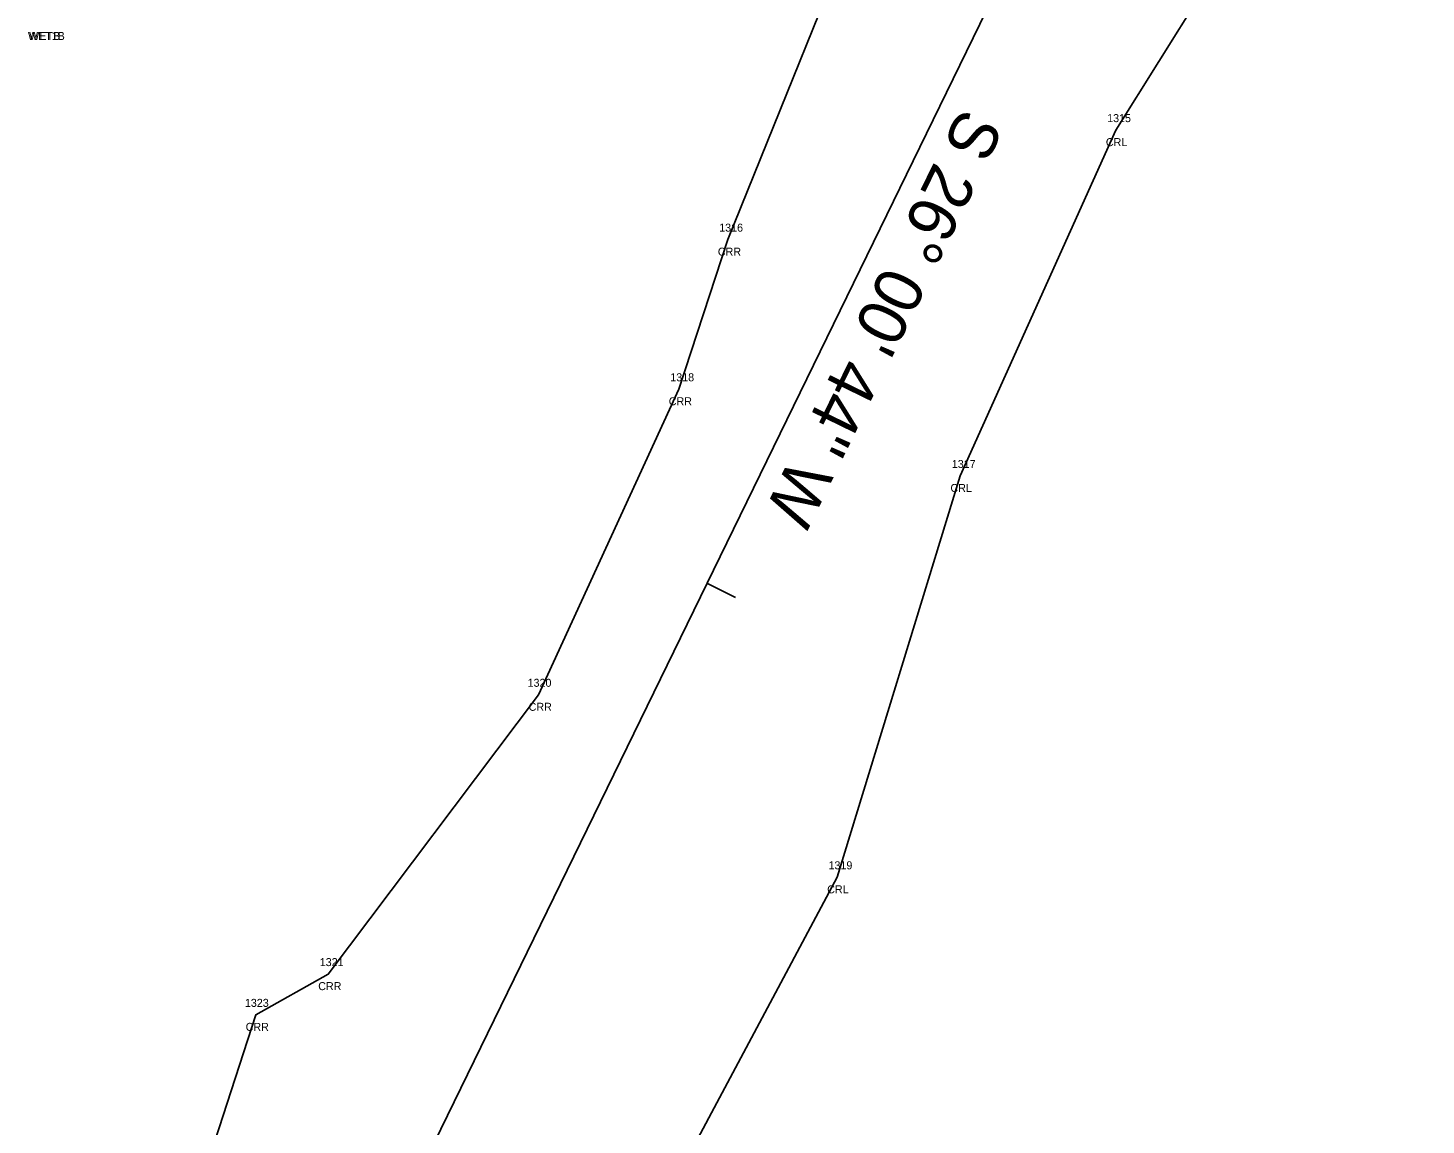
# Model space of a CAD drawing. Extents: x 1964982 to 1970452, y 1116335 to 1119906.
# Drawn here: x 1967698.9 to 1967873.6, y 1117597.5 to 1117734.5 of the extents above; entities that cross this region are included whole.
import ezdxf

# ---------------------------------------------------------------- set-up
doc = ezdxf.new("R2010")
doc.units = 0
for name, color, linetype in [('RD_EX_DV_Prop', 7, 'Continuous'), ('RD_EX_H2O', 7, 'Continuous'), ('RD_EX_H2O_txCode', 7, 'Continuous'), ('RD_EX_H2O_WetLd_txCode', 7, 'Continuous'), ('RD_HC_CL', 7, 'Continuous'), ('RD_HC_Data', 7, 'Continuous'), ('RD_SMD_Locator', 7, 'Continuous')]:
    doc.layers.add(name, color=color, linetype=linetype)

msp = doc.modelspace()

# ---------------------------------------------------------------- linework, layer by layer
at = {"layer": 'RD_EX_DV_Prop'}
msp.add_line((1967849.81, 1117800.6), (1967729.31, 1117553.65), dxfattribs=at)
at = {"layer": 'RD_EX_H2O'}
for points in [[(1967794.3, 1117875.45), (1967796.63, 1117853.43), (1967809.67, 1117835.4), (1967828.83, 1117808.28), (1967805.08, 1117754.56), (1967786.33, 1117708.04), (1967780.19, 1117689.35), (1967762.68, 1117651.19), (1967736.39, 1117616.3), (1967727.33, 1117611.21), (1967715.04, 1117573.35), (1967731.01, 1117514.73), (1967775.86, 1117468.11), (1967793.29, 1117458.88), (1967816.39, 1117454.18)], [(1967873.55, 1117813.3), (1967873.54, 1117810.73), (1967868.98, 1117791.48), (1967856.29, 1117756.05), (1967834.78, 1117721.72), (1967815.36, 1117678.52), (1967799.96, 1117628.39), (1967778.25, 1117587.63), (1967771.33, 1117582.11), (1967756.46, 1117564.6), (1967764.36, 1117543.85), (1967795.97, 1117517.33), (1967805.92, 1117513.21), (1967828.95, 1117503.56)]]:
    msp.add_lwpolyline(points, dxfattribs=at)
at = {"layer": 'RD_HC_CL'}
msp.add_line((1967849.81, 1117800.6), (1967729.31, 1117553.65), dxfattribs=at)
at = {"layer": 'RD_HC_Data'}
msp.add_line((1967783.7, 1117665.12), (1967787.29, 1117663.36), dxfattribs=at)
at = {"layer": 'RD_SMD_Locator'}
for centre in [(1967834.78, 1117721.72), (1967786.33, 1117708.04), (1967780.19, 1117689.35), (1967815.36, 1117678.52), (1967762.68, 1117651.19), (1967799.96, 1117628.39), (1967736.39, 1117616.3), (1967727.33, 1117611.21)]:
    msp.add_circle(centre, 0.001, dxfattribs=at)

# ---------------------------------------------------------------- texts
at = {"layer": 'RD_EX_H2O_txCode'}
for s, p in [('1315', (1967833.71, 1117722.72)), ('CRL', (1967833.55, 1117719.72)), ('1316', (1967785.24, 1117709.04)), ('CRR', (1967785.07, 1117706.04)), ('1318', (1967779.13, 1117690.35)), ('CRR', (1967778.94, 1117687.35)), ('1317', (1967814.3, 1117679.52)), ('CRL', (1967814.13, 1117676.52)), ('1320', (1967761.3, 1117652.19)), ('CRR', (1967761.43, 1117649.19)), ('1319', (1967798.9, 1117629.39)), ('CRL', (1967798.73, 1117626.39)), ('1321', (1967735.33, 1117617.3)), ('CRR', (1967735.14, 1117614.3)), ('1323', (1967725.98, 1117612.21)), ('CRR', (1967726.07, 1117609.21))]:
    msp.add_text(s, height=1, dxfattribs=at).set_placement(p)
at = {"layer": 'RD_EX_H2O_WetLd_txCode'}
for s, p in [('WET1B', (1967698.87, 1117732.98)), ('WETB', (1967699.03, 1117732.98))]:
    msp.add_text(s, height=1, dxfattribs=at).set_placement(p)
at = {"layer": 'RD_HC_Data'}
msp.add_text('S 26° 00\' 44" W', height=6, rotation=243.9877, dxfattribs=at).set_placement((1967815.5, 1117724.74))

doc.saveas('drawing.dxf')
